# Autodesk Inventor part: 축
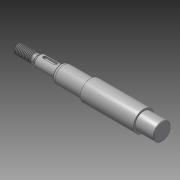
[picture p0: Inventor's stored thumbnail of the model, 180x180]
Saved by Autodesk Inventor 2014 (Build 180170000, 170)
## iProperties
Created: 2015-11
Part Number: 축
Material: 강철, 연강
Document SubType Name: Modeling
Designer: mduedu
Density: 1 g/cm^3
Appearance: 강철
Author: mduedu
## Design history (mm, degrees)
sketch "스케치1"
  geometry: L1 (-86, 0)-(86, 0); L2 (-86, 0)-(-86, 4); L3 (-86, 4)-(-70.732, 4); L4 (-70.732, 4)-(-69, 3); L5 (-69, 3)-(-67, 3); L6 (-67, 3)-(-67, 5); L7 (-67, 5)-(-49, 5); L8 (-49, 5)-(-49, 6.55); L9 (-47.355, 7.5)-(-23, 7.5); L10 (-23, 7.5)-(-23, 9); L11 (0, 0)-(0, 9); L12 (86, 4)-(70.732, 4); L13 (70.732, 4)-(69, 3); L14 (69, 3)-(67, 3); L15 (67, 3)-(67, 5); L16 (67, 5)-(49, 5); L17 (23, 7.5)-(23, 9); L18 (86, 0)-(86, 4); L19 (-23, 9)-(23, 9); L20 (-49, 6.55)-(-47.355, 7.5); L21 (47.355, 7.5)-(23, 7.5); L22 (49, 6.55)-(47.355, 7.5); L23 (49, 5)-(49, 6.55); 1 further point
  constraints: 46 end point, 10 symmetric about line, 6 perpendicular, 5 parallel, 2 midpoint, 1 coincident, 1 horizontal
  dimensions: "d0" = 172 distance of L1.start L1.end (derived); "d1" = 8 diameter of L3 L1; "d2" = 30 deg angle of L4 L5; "d3" = 6 diameter of L5 L1; "d4" = 10 diameter of L7 L1; "d5" = 15 diameter of L9 L1; "d6" = 18 diameter of L19 L1; "d8" = 18 distance of L6.end L7.end; "d9" = 46 distance of L10.end L17.end; "d10" = 2 distance of L4.end L5.end; "d11" = 17 distance from line of L4.end L2; "d16" = 13.1 diameter of L8.end L1; "d17" = 30 deg angle of L20 L9; "d18" = 26 distance between parallel lines of L10 L8
revolve "회전1" sketch "스케치1" stored, may be unused: angle "d12" = 90 deg
chamfer "모따기1" distance "d13" = 0.5; stored, may be unused: second distance "d14" = 2, angle "d15" = 45 deg
fillet "모깎기1" dims "d19" = 4, "d20" = 0.5
node "작업 평면1"
sketch "스케치2" dims "d23" = 12
  geometry: L1 (-4.5, 1.5)-(4.5, 1.5); L2 (4.5, 1.5)-(4.5, -1.5); L3 (4.5, -1.5)-(-4.5, -1.5); L4 (-4.5, -1.5)-(-4.5, 1.5); L5 (-9, -4.5)-(-9, 4.5) reference; 3 further points
  constraints: 8 end point, 2 midpoint, 2 parallel, 2 vertical alignment, 1 horizontal, 1 perpendicular, 4 other
  dimensions: "d21" = 3 distance between parallel lines of L3 L1; "d24" = 3 dimension on L5
extrude "돌출1" cut sketch "스케치2" distance "d25" = 1.8; taper "d26" = 0 deg
feature "스레드1" dims "d27" = 10, "d28" = 0
feature "스레드2" dims "d29" = 10, "d30" = 0
chamfer "모따기2" distance "d31" = 0.5; stored, may be unused: second distance "d32" = 2, angle "d33" = 45 deg
node "작업 평면2"
sketch "스케치3"
  geometry: C1 r 7.5 at (0, 0) reference; 1 further point
extrude "돌출2" cut sketch "스케치3" stored distance "d36" = 10; taper "d37" = 0 deg
chamfer "모따기3" distance "d38" = 0.5; stored, may be unused: second distance "d39" = 2, angle "d40" = 45 deg
fillet "모깎기3" dims "d41" = 0.6
node "솔리드1"
mirror "대칭1"
node "절단 모서리 투영1"
other parameters: "d35" = 16
